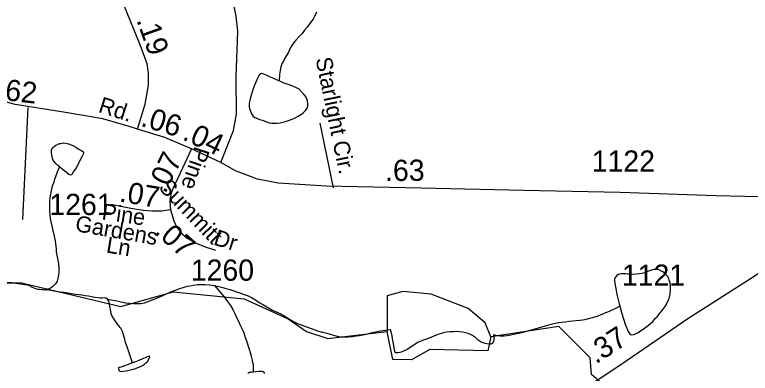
# Model space of a CAD drawing. Extents: x 2001466 to 2224147, y 644118 to 847247.
# Drawn here: x 2041705 to 2046028, y 663505 to 665614 of the extents above; entities that cross this region are included whole.
import ezdxf

# ---------------------------------------------------------------- set-up
doc = ezdxf.new("R2010")
doc.units = 0
for name, color, linetype in [('Exist Hydrographic Misc Water Feature', 7, 'Continuous'), ('Exist Road Non-System Type 51', 7, 'Continuous'), ('Exist Road Non-System Type 51 Label', 7, 'Continuous'), ('Exist Road Secondary Mileage Hundredths English Label', 7, 'Continuous'), ('Exist Road Secondary Type 51 Attributed', 7, 'Continuous'), ('Exist Road Secondary Type 51 Label', 7, 'Continuous'), ('Exist Road Secondary Type 51 Number Label', 7, 'Continuous')]:
    doc.layers.add(name, color=color, linetype=linetype)

msp = doc.modelspace()

# ---------------------------------------------------------------- linework, layer by layer
at = {"layer": 'Exist Hydrographic Misc Water Feature'}
for points in [[(2043479.1, 665628.4), (2043469.1, 665606.4), (2043459.2, 665588.4), (2043449.2, 665576.4), (2043439.2, 665562.4), (2043423.4, 665540.4), (2043407.4, 665522.3), (2043393.4, 665504.3), (2043375.4, 665484.2), (2043357.5, 665464.2), (2043347.5, 665452.2), (2043333.6, 665432.2), (2043323.5, 665416.2), (2043313.7, 665394.2), (2043301.6, 665374.2), (2043291.5, 665358.1), (2043281.7, 665336.1), (2043275.7, 665324.1), (2043269.8, 665308.1), (2043265.7, 665286.1), (2043261.8, 665262.1), (2043259.9, 665224.1)], [(2043259.9, 665224.1), (2043253.8, 665226.1), (2043239.8, 665232), (2043221.8, 665240), (2043207.9, 665246), (2043187.8, 665255.9), (2043169.9, 665263.9), (2043153.9, 665267.9), (2043145.9, 665263.9), (2043139.8, 665255.9), (2043133.8, 665243.9), (2043121.9, 665217.8), (2043111.9, 665193.8), (2043102, 665165.8), (2043096.1, 665145.8), (2043088.1, 665119.8), (2043082.2, 665091.8), (2043082.2, 665069.8), (2043084.2, 665061.8), (2043090.2, 665045.8), (2043096.3, 665031.8), (2043104.3, 665019.8), (2043116.4, 665009.8), (2043132.4, 665003.9), (2043144.3, 664997.9), (2043160.3, 664993.9), (2043174.4, 664988), (2043200.3, 664978), (2043216.3, 664976), (2043232.3, 664976.1), (2043246.4, 664976.1), (2043264.2, 664978.2), (2043280.4, 664982.2), (2043296.4, 664986.2), (2043320.4, 664994.2), (2043344.4, 665004.3), (2043370.3, 665016.4), (2043380.3, 665022.4), (2043390.1, 665028.4), (2043400.2, 665036.3), (2043414.1, 665050.4), (2043424.2, 665064.4), (2043428.1, 665076.4), (2043428.1, 665092.4), (2043426, 665106.4), (2043422.1, 665118.4), (2043412.1, 665136.4), (2043402, 665148.4), (2043392, 665158.4), (2043376, 665176.3), (2043358, 665186.3), (2043344, 665192.2), (2043330.1, 665198.2), (2043299.9, 665208.1), (2043281.9, 665214.1), (2043259.9, 665224.1)], [(2041967.1, 664719.7), (2041963.2, 664725.7), (2041957, 664729.7), (2041949, 664737.7), (2041934.9, 664751.7), (2041931, 664757.7), (2041926.9, 664767.7), (2041925.1, 664777.6), (2041923, 664789.6), (2041920.9, 664799.6), (2041920.9, 664817.6), (2041922.8, 664823.6), (2041928.9, 664831.6), (2041936.9, 664839.7), (2041946.8, 664845.7), (2041956.8, 664849.7), (2041968.9, 664855.7), (2041978.8, 664855.7), (2041990.9, 664859.7), (2042002.8, 664857.8), (2042012.8, 664855.8), (2042020.8, 664853.8), (2042036.8, 664847.9), (2042051, 664841.9), (2042064.9, 664833.9), (2042076.8, 664825.9), (2042088.9, 664819.9), (2042098.9, 664813.9), (2042108.8, 664808), (2042108.8, 664802), (2042106.9, 664794), (2042101, 664782), (2042093, 664767.9), (2042082.9, 664745.9), (2042065.1, 664714), (2042051.2, 664691.9), (2042041.1, 664673.9), (2042033.1, 664669.9), (2042023.1, 664673.9), (2042007.1, 664687.8), (2041991.1, 664699.8), (2041971.2, 664715.7), (2041967.1, 664719.7)], [(2041967.1, 664719.7), (2041955.2, 664687.8), (2041945.1, 664659.7), (2041939.2, 664645.7), (2041935.3, 664629.7), (2041925.3, 664605.7), (2041919.3, 664579.7), (2041915.4, 664557.7), (2041911.3, 664537.7), (2041909.5, 664517.7), (2041909.5, 664491.7), (2041909.7, 664459.7), (2041911.5, 664433.7), (2041915.6, 664405.7), (2041919.7, 664387.7), (2041925.7, 664361.7), (2041929.8, 664343.7), (2041933.9, 664323.7), (2041937.8, 664301.7), (2041941.9, 664283.8), (2041943.9, 664267.8)], [(2041943.9, 664267.8), (2041946, 664249.8), (2041948, 664237.8), (2041948, 664221.8), (2041949.9, 664207.8), (2041954.2, 664189.8), (2041956, 664179.8), (2041958.1, 664169.8), (2041960.1, 664159.8), (2041962.2, 664145.8), (2041964, 664125.8), (2041964.2, 664115.8), (2041964.2, 664099.8), (2041962.2, 664083.8), (2041960.1, 664071.8), (2041958.3, 664061.8), (2041956.4, 664053.8), (2041954.4, 664045.8), (2041948.4, 664037.8), (2041944.3, 664031.8), (2041936.3, 664023.8), (2041932.2, 664019.8), (2041926.3, 664013.8), (2041914.4, 664005.8), (2041906.4, 664001.8), (2041900.2, 663999.8), (2041893.9, 663995.3), (2041890.4, 663995.8)], [(2045261.9, 663900.1), (2045274, 663856.1), (2045292.2, 663794.1), (2045310.3, 663750.2), (2045322.4, 663732.2), (2045332.2, 663730.2), (2045344.3, 663732.3), (2045366.2, 663742.3), (2045386.1, 663756.3), (2045406.2, 663770.3), (2045422.2, 663782.4), (2045440.1, 663796.4), (2045456, 663810.4), (2045472, 663828.4), (2045480, 663836.4), (2045490.1, 663850.5), (2045497.9, 663860.5), (2045507.9, 663872.5), (2045515.9, 663882.5), (2045528, 663898.6), (2045541.8, 663922.6), (2045551.8, 663946.6), (2045557.8, 663970.6), (2045559.6, 663996.6), (2045559.6, 664018.6), (2045557.8, 664032.6), (2045555.7, 664042.6), (2045551.6, 664052.6), (2045549.6, 664060.6), (2045543.6, 664074.6), (2045533.6, 664084.5), (2045525.6, 664094.5), (2045517.6, 664100.5), (2045505.5, 664106.4), (2045491.5, 664112.4), (2045477.6, 664114.4), (2045461.6, 664114.4), (2045441.5, 664110.3), (2045423.6, 664104.3), (2045405.6, 664096.3), (2045391.5, 664092.3), (2045377.5, 664090.3), (2045359.5, 664088.2), (2045335.5, 664086.1), (2045321.5, 664088.1), (2045307.6, 664088.1), (2045297.5, 664090.1), (2045285.6, 664090.1), (2045269.4, 664090), (2045259.6, 664088), (2045253.5, 664086), (2045243.6, 664080), (2045233.8, 664067.9), (2045229.7, 664057.9), (2045229.7, 664049.9), (2045231.7, 664034), (2045237.9, 664004), (2045243.8, 663968), (2045258, 663914.1), (2045261.9, 663900.1)], [(2039146.4, 663342.5), (2039263.3, 663386), (2039620.3, 663861.1), (2039695.3, 663928.5), (2039828.4, 663961.9), (2040303.3, 663919.5), (2040537.3, 663786.7), (2041161.2, 663921.7), (2041453.4, 664047), (2041744.4, 664037.8), (2042328.4, 663898), (2042636.4, 663983.7), (2043053.2, 663942.3), (2043311.4, 663825.5), (2043420.3, 663751.1), (2043545.4, 663709.3), (2043894.4, 663751.3)], [(2041496.5, 664017), (2041522.5, 664021), (2041540.4, 664023), (2041560.5, 664027.1), (2041576.3, 664029.1), (2041604.3, 664033.2), (2041624.2, 664035.2), (2041650.3, 664037.2), (2041678.4, 664037.3), (2041694.4, 664037.4), (2041710.4, 664035.4), (2041724.3, 664033.4), (2041738.2, 664031.4), (2041752.4, 664029.4), (2041764.3, 664027.5), (2041780.3, 664025.5), (2041790.3, 664021.5), (2041796.3, 664019.5), (2041802.4, 664013.5), (2041808.4, 664011.5), (2041816.4, 664007.6), (2041826.4, 664003.6), (2041832.4, 664001.6), (2041840.4, 663999.6)], [(2041840.4, 663999.6), (2041854.5, 663999.6), (2041866.4, 663997.7), (2041876.5, 663997.7), (2041884.4, 663995.7), (2041890.4, 663995.8)], [(2042468.4, 663918.8), (2042518.3, 663938.9), (2042544.3, 663949), (2042572.4, 663961), (2042596.4, 663973.1), (2042622.2, 663983.1), (2042650.3, 663993.1), (2042670.2, 664001.2), (2042700.1, 664011.2), (2042720.2, 664017.2), (2042736.2, 664019.3), (2042754.3, 664023.3), (2042778.3, 664027.4), (2042798.2, 664027.4), (2042822.2, 664027.4), (2042852.3, 664025.5), (2042878.1, 664021.6)], [(2042878.1, 664021.6), (2042892.3, 664017.6), (2042912.2, 664013.7), (2042928.2, 664009.7), (2042946.2, 664003.7), (2042970.2, 663997.8), (2042992.1, 663989.8), (2043008.1, 663983.8), (2043028.2, 663977.8), (2043054.3, 663967.9), (2043076.2, 663960), (2043096.3, 663950), (2043120.3, 663936), (2043142.2, 663922.1), (2043166.2, 663908.2), (2043196.4, 663890.2), (2043220.4, 663876.2), (2043238.4, 663868.3), (2043268.3, 663854.3), (2043296.4, 663838.4), (2043320.4, 663822.4), (2043346.5, 663808.4), (2043370.5, 663796.6), (2043394.5, 663788.6), (2043420.5, 663778.7), (2043458.6, 663764.7), (2043478.5, 663756.7), (2043512.6, 663746.8), (2043530.6, 663742.8), (2043552.5, 663736.9), (2043578.6, 663728.9), (2043600.5, 663723), (2043622.5, 663719), (2043644.6, 663719), (2043664.5, 663719.1), (2043692.6, 663721.1), (2043714.5, 663725.1), (2043728.5, 663727.2), (2043750.6, 663731.2), (2043778.5, 663737.3), (2043808.5, 663745.3), (2043826.5, 663749.4), (2043842.5, 663753.4), (2043870.4, 663757.5), (2043914.5, 663761.5)], [(2042878.1, 664021.6), (2042902.1, 663993.7), (2042922.2, 663969.7), (2042936.4, 663953.7), (2042956.3, 663927.7), (2042972.3, 663903.8), (2042986.4, 663879.8), (2042998.5, 663855.8), (2043008.3, 663833.8), (2043020.6, 663811.9), (2043028.6, 663791.9), (2043040.5, 663767.9), (2043048.7, 663748), (2043054.7, 663730), (2043060.6, 663712), (2043068.6, 663690), (2043080.7, 663652), (2043084.8, 663640), (2043088.7, 663628), (2043094.9, 663606), (2043099, 663590.1), (2043101, 663578.1), (2043102.9, 663568.1), (2043107, 663558.1), (2043107, 663544.1), (2043107, 663536.1), (2043107, 663512.1)], [(2042250.5, 663940.4), (2042240.4, 663946.4), (2042232.4, 663948.4), (2042218.5, 663946.3), (2042206.4, 663946.3), (2042190.4, 663948.3), (2042176.4, 663950.2), (2042156.3, 663954.2), (2042138.5, 663958.2), (2042118.4, 663960.1), (2042098.5, 663964.1), (2042082.5, 663966.1), (2042062.4, 663968.1), (2042048.5, 663970), (2042028.4, 663974), (2041994.4, 663979.9), (2041972.4, 663981.9), (2041934.5, 663987.8), (2041916.4, 663991.8), (2041904.5, 663993.8), (2041893.9, 663995.3), (2041890.4, 663995.8)], [(2044152.3, 663969.3), (2043986.2, 663985.7), (2043894.4, 663961.4), (2043894.4, 663751.3)], [(2044503.4, 663719.3), (2044469.3, 663802), (2044369.3, 663886.1), (2044152.3, 663969.3)], [(2042250.5, 663940.4), (2042314.4, 663928.5), (2042338.4, 663922.6), (2042358.5, 663918.6), (2042380.5, 663916.6), (2042402.4, 663914.7), (2042426.4, 663914.8), (2042446.5, 663914.8), (2042468.4, 663918.8)], [(2042397.1, 663566.7), (2042379, 663618.7), (2042374.9, 663630.7), (2042364.9, 663660.7), (2042356.9, 663686.6), (2042352.8, 663704.6), (2042348.9, 663716.6), (2042344.8, 663730.6), (2042338.8, 663750.6), (2042328.6, 663770.6), (2042314.6, 663786.6), (2042304.6, 663800.5), (2042294.8, 663812.5), (2042276.5, 663844.4), (2042272.6, 663854.4), (2042270.6, 663868.4), (2042268.5, 663882.4), (2042264.4, 663898.5), (2042262.4, 663912.5), (2042256.4, 663932.5), (2042250.5, 663940.4)], [(2044942.2, 663807.5), (2044964.1, 663811.5), (2045004.1, 663815.6), (2045026.3, 663817.6), (2045044.1, 663819.7), (2045064.2, 663823.7), (2045086.1, 663829.8), (2045108.1, 663835.8), (2045130, 663841.8), (2045152, 663849.9), (2045167.9, 663855.9), (2045180, 663861.9), (2045190.1, 663866), (2045200.1, 663870), (2045212, 663876), (2045226, 663882), (2045237.9, 663888), (2045250, 663894), (2045261.9, 663900.1)], [(2044518.3, 663732.7), (2044536.4, 663726.7), (2044546.4, 663726.7), (2044558.3, 663724.7), (2044570.4, 663724.8), (2044582.3, 663724.8), (2044596.5, 663726.9), (2044608.4, 663728.9), (2044620.5, 663730.9), (2044656.3, 663738.9), (2044686.3, 663745), (2044720.3, 663755.1), (2044758.3, 663765.1), (2044788.4, 663773.2), (2044818.3, 663781.3), (2044838.2, 663787.3), (2044866.1, 663795.3), (2044884.2, 663799.4), (2044902.2, 663803.4), (2044920.2, 663805.4), (2044942.2, 663807.5)], [(2044503.4, 663719.3), (2044486.4, 663637.6), (2044145.4, 663644.6), (2044036.3, 663584.4), (2043928.2, 663586.7), (2043894.4, 663751.3)], [(2044518.3, 663732.7), (2044518.3, 663728.7), (2044520.4, 663714.7), (2044520.4, 663704.7), (2044518.3, 663694.7), (2044516.5, 663688.7), (2044510.6, 663680.7), (2044502.6, 663676.7), (2044492.5, 663676.7), (2044480.6, 663678.6), (2044470.6, 663680.6), (2044446.4, 663688.5), (2044428.3, 663700.5), (2044408.4, 663718.5), (2044392.4, 663728.4), (2044376.4, 663736.4), (2044362.5, 663740.4), (2044346.5, 663744.4), (2044334.4, 663746.4), (2044318.4, 663748.3), (2044300.4, 663750.3), (2044288.5, 663748.3), (2044262.4, 663748.3), (2044242.3, 663746.2), (2044224.5, 663742.1), (2044210.4, 663738.1), (2044192.5, 663732.1), (2044168.5, 663724.1), (2044154.4, 663718), (2044130.6, 663708), (2044102.5, 663697.9), (2044074.6, 663685.9), (2044010.6, 663645.7), (2043994.6, 663637.7), (2043982.7, 663631.7), (2043968.6, 663627.7), (2043956.7, 663625.7), (2043944.6, 663625.7), (2043938.7, 663633.6), (2043930.5, 663677.6), (2043920.6, 663733.6), (2043914.5, 663761.5)], [(2045216.5, 663312.6), (2045153.2, 663446.9), (2045095.4, 663497.3), (2045086.3, 663596), (2044903.2, 663780.1), (2044503.4, 663719.3)], [(2042397.1, 663566.7), (2042381.1, 663560.7), (2042351.1, 663548.6), (2042329.2, 663540.6), (2042313.2, 663536.5), (2042315.3, 663532.5), (2042319.2, 663518.7), (2042325.1, 663516.7), (2042335.2, 663514.6), (2042355.2, 663518.7), (2042369.2, 663520.7), (2042385.2, 663524.8), (2042403.2, 663528.8), (2042417.2, 663532.8), (2042425.2, 663536.8), (2042447.1, 663546.8), (2042455.1, 663550.9), (2042467, 663558.9), (2042475, 663566.9), (2042485, 663574.9), (2042495.1, 663590.9), (2042499, 663600.9), (2042494.9, 663604.9), (2042489.1, 663602.9), (2042479.1, 663598.9), (2042471.1, 663594.9), (2042461.1, 663590.9), (2042439.1, 663582.8), (2042421.1, 663574.7), (2042403, 663568.7), (2042397.1, 663566.7)], [(2043107, 663512.1), (2043099, 663512.1), (2043091, 663510.1), (2043087.1, 663510), (2043083, 663510), (2043079.1, 663508), (2043075, 663504)], [(2043175, 663504.2), (2043171.2, 663510.2), (2043165, 663514.2), (2043159.1, 663516.2), (2043151.1, 663516.1), (2043139, 663516.1), (2043121.1, 663514.1), (2043107, 663512.1)]]:
    msp.add_lwpolyline(points, dxfattribs=at)
at = {"layer": 'Exist Road Non-System Type 51'}
for p, q in [((2041782.7, 665068.5), (2041750.3, 664409.4)), ((2043577.8, 664596.6), (2043500, 664976.6))]:
    msp.add_line(p, q, dxfattribs=at)
at = {"layer": 'Exist Road Secondary Type 51 Attributed'}
for points in [[(2042916.6, 664745.2), (2042991.5, 664933.2), (2043008.4, 665028.3), (2043006.3, 665248), (2043015.3, 665517.4), (2043005.8, 665606.1), (2042984.2, 665711.8), (2042952.5, 665806.8), (2042935.6, 665896.6), (2042933.5, 666044.5), (2042941.4, 666425.8), (2042954.1, 666810.3), (2042957.8, 667060.7), (2042989.4, 667238.2), (2043010, 667446.3), (2043014.2, 667688.2), (2043022.2, 667912.1)], [(2042427.2, 664940.4), (2042370.9, 664957.5), (2042223.1, 665001.9), (2041979.2, 665042), (2041707.4, 665085.4), (2041570.2, 665123.4), (2041409.7, 665193.1), (2041265.6, 665290.3), (2041097.8, 665437.1), (2040889.8, 665624.1), (2040685.6, 665824.8), (2040565.3, 665932.5), (2040481.9, 665975.8), (2040371, 666018.1), (2040208.5, 666063.5), (2039941.9, 666139.6)], [(2042427.2, 664940.4), (2042472.3, 665088.2), (2042491.8, 665198.6), (2042491.8, 665271), (2042483.2, 665324.7), (2042442.7, 665437.1), (2042249.2, 665909.3)], [(2042744.8, 664826), (2042586.7, 664892), (2042427.2, 664940.4)], [(2042744.8, 664826), (2042690, 664710.8), (2042662.3, 664648.9), (2042637.8, 664599), (2042625.9, 664570.1), (2042619.1, 664539.5), (2042617.4, 664517.5), (2042620.8, 664466.5)], [(2042916.6, 664745.2), (2042744.8, 664826)], [(2046166.9, 664540.4), (2045826.4, 664547.7), (2045262.7, 664568.8), (2044697.4, 664579.4), (2044094.6, 664593.1), (2043535.7, 664604.7), (2043253.3, 664623.7), (2043130.9, 664647), (2043003.2, 664696.6), (2042916.6, 664745.2)], [(2042620.8, 664466.5), (2042568.2, 664458.1), (2042513.8, 664458.1), (2042459.4, 664463.1), (2042388.1, 664475), (2042269.2, 664497.1)], [(2042620.8, 664466.5), (2042639.5, 664402), (2042658.2, 664363), (2042687.1, 664327.3), (2042717.7, 664300.2), (2042766.9, 664271.3), (2042824.7, 664249.2), (2042884, 664228.9)], [(2046205.8, 664180.3), (2046050.1, 664073.4), (2045655.3, 663822), (2045273.2, 663557.9), (2044862.6, 663285.4), (2044725.9, 663177.6), (2044659.4, 663119.5), (2044612.9, 663073)]]:
    msp.add_lwpolyline(points, dxfattribs=at)

# ---------------------------------------------------------------- texts
at = {"layer": 'Exist Road Non-System Type 51 Label'}
msp.add_text('Starlight Cir.', height=95, rotation=281.5703, dxfattribs=at).set_placement((2043472.8, 665354.5))
at = {"layer": 'Exist Road Secondary Mileage Hundredths English Label'}
for s, rotation, p in [('.19', 289.8106, (2042419, 665582.4)), ('.62', 353.2639, (2041597.7, 665117.2)), ('.06', 343.1226, (2042440, 664961)), ('.04', 334.8186, (2042684.8, 664882)), ('.07', 63.9078, (2042589.2, 664557)), ('.63', 0.5387, (2043882.1, 664634.9)), ('.07', 350.5443, (2042315.2, 664515.1)), ('.07', 318.3865, (2042520.2, 664331.2)), ('.37', 32.8224, (2045120.6, 663557))]:
    msp.add_text(s, height=125, rotation=rotation, dxfattribs=at).set_placement(p)
at = {"layer": 'Exist Road Secondary Type 51 Label'}
for s, rotation, p in [('Rd.', 342.2481, (2042191.1, 665042.8)), ('Pine', 251.3245, (2042763.1, 664845.2)), ('Summitt', 313.7135, (2042545.5, 664594.2)), ('Pine', 351.7147, (2042213.1, 664410.2)), ('Gardens', 350.1258, (2042055.9, 664341.6)), ('Dr', 342.2481, (2042867.9, 664262.9)), ('Ln', 350.6789, (2042238.6, 664215.7))]:
    msp.add_text(s, height=95, rotation=rotation, dxfattribs=at).set_placement(p)
at = {"layer": 'Exist Road Secondary Type 51 Number Label'}
for s, p in [('1122', (2045096.1, 664690.5)), ('1261', (2041908.3, 664435.5)), ('1260', (2042739.7, 664049.1)), ('1121', (2045273.4, 664019.6))]:
    msp.add_text(s, height=125, dxfattribs=at).set_placement(p)

doc.saveas('drawing.dxf')
